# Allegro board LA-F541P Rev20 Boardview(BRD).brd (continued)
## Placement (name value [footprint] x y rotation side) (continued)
CT152  2.2U_0402_6.3V6M  [C_0402]  20.83 53.47 270 bottom
CT153  1U_0603_25V6  [C_0603]  26.06 65.83 180 bottom
CT157  1U_0603_25V6  [C_0603]  27.32 60.34 0 bottom
CT158  0.22U_0402_10V6K  [C_0402]  23.06 58.68 0 top
CT159  220P_0402_50V7K  [C_0402]  25.34 62.22 90 top
CT160  220P_0402_50V7K  [C_0402]  26.84 61.79 90 top
CT163  1U_0201_6.3V6M  [C_0201]  28.44 39.42 180 top
CT164  47U_0603_6.3V6M  [C_0603]  31.24 35.05 0 top
CT165  47U_0603_6.3V6M  [C_0603]  31.24 33.78 0 top
CT174  0.22U_0201_6.3V6M  [C_0201]  31.15 33.1 270 bottom
CT175  0.22U_0201_6.3V6M  [C_0201]  30.57 33.1 270 bottom
CT176  0.22U_0201_6.3V6M  [C_0201]  34.25 32.84 0 bottom
CT177  0.22U_0201_6.3V6M  [C_0201]  34.25 33.4 0 bottom
CT178  0.22U_0201_6.3V6M  [C_0201]  29.31 32.53 90 bottom
CT179  0.22U_0201_6.3V6M  [C_0201]  35.98 31.7 180 bottom
CT180  0.22U_0201_6.3V6M  [C_0201]  29.9 32.53 90 bottom
CT181  0.22U_0201_6.3V6M  [C_0201]  35.98 32.26 180 bottom
CT182  39P_0201_50V8J  [C_0201]  21.19 46.62 180 bottom
CT183  100P_0201_50V8J  [C_0201]  21.19 47.19 180 bottom
CT184  39P_0201_50V8J  [C_0201]  23.5 37.57 270 top
CT185  100P_0201_50V8J  [C_0201]  22.8 36.42 270 top
CT186  39P_0201_50V8J  [C_0201]  23.37 46.61 0 bottom
CT187  100P_0201_50V8J  [C_0201]  23.37 47.18 0 bottom
CT188  4.7U_0603_25V6K  [C_0603]  28.46 53.21 0 bottom
CT189  10U_0402_6.3V6M  [C_0402]  15.69 51.62 90 bottom
CV156  8.2P_0402_50V8D  [C_0402]  51.89 29.47 180 top
CV157  10U_0603_6.3V6M  [C_0603]  52.13 28.32 180 top
CV158  0.1U_0201_10V6K  [C_0201]  62.61 27.52 90 bottom
CV159  0.1U_0201_10V6K  [C_0201]  63.25 27.52 90 bottom
CV160  0.1U_0201_10V6K  [C_0201]  64.9 27.52 90 bottom
CV161  0.1U_0201_10V6K  [C_0201]  65.53 27.52 90 bottom
CV162  0.1U_0201_10V6K  [C_0201]  66.17 27.52 90 bottom
CV163  0.1U_0201_10V6K  [C_0201]  66.8 27.52 90 bottom
CV164  0.1U_0201_10V6K  [C_0201]  67.57 27.52 90 bottom
CV165  0.1U_0201_10V6K  [C_0201]  68.2 27.52 90 bottom
CV166  0.1U_0201_10V6K  [C_0201]  61.98 27.52 90 bottom
CV167  0.1U_0201_10V6K  [C_0201]  61.34 27.52 90 bottom
CV168  1000P_0402_50V7K  [C_0402]  42.55 34.21 90 top
CV169  0.1U_0402_25V6  [C_0402]  46.11 35.87 180 top
CV178  0.1U_0201_10V6K  [C_0201]  14.63 91.38 90 top
CV179  10U_0402_6.3V6M  [C_0402]  15.39 91.34 90 top
CV180  0.1U_0201_25V6K  [C_0201]  14.61 93.38 270 top
CV181  0.1U_0201_25V6K  [C_0201]  14.69 77.77 180 bottom
CV182  0.1U_0201_25V6K  [C_0201]  15.35 77.33 90 bottom
CV183  .1U_0402_16V7K  [C_0402]  55.17 30.07 180 bottom
CV184  8.2P_0402_50V8D  [C_0402]  53.69 29.15 270 bottom
CV499  0.1U_0402_10V7K  [C_0402]  245.89 48.05 90 top
CV794  0.1U_0402_10V7K  [C_0402]  235.59 52.38 90 top
CV796  1U_0402_6.3V6K  [C_0402]  236.48 52.38 90 top
CV798  4.7U_0603_6.3V6K  [C_0603]  237.62 52.26 90 top
CV817  0.1U_0402_10V7K  [C_0402]  208.64 51.66 0 top
CV818  0.22U_0201_6.3V6M  [C_0201]  191.42 65.95 180 top
CV819  0.22U_0201_6.3V6M  [C_0201]  191.42 65.31 180 top
CV820  0.22U_0201_6.3V6M  [C_0201]  193.07 66.96 180 top
CV821  0.22U_0201_6.3V6M  [C_0201]  193.07 66.33 180 top
CV822  0.22U_0201_6.3V6M  [C_0201]  191.42 67.35 180 top
CV823  0.22U_0201_6.3V6M  [C_0201]  191.42 67.98 180 top
CV824  0.22U_0201_6.3V6M  [C_0201]  193.07 69 180 top
CV825  0.22U_0201_6.3V6M  [C_0201]  193.07 68.36 180 top
CV826  0.22U_0201_6.3V6M  [C_0201]  191.42 69.38 180 top
CV827  0.22U_0201_6.3V6M  [C_0201]  191.42 70.01 180 top
CV828  0.22U_0201_6.3V6M  [C_0201]  193.07 71.03 180 top
CV829  0.22U_0201_6.3V6M  [C_0201]  193.07 70.39 180 top
CV830  0.22U_0201_6.3V6M  [C_0201]  191.42 71.41 180 top
CV831  0.22U_0201_6.3V6M  [C_0201]  191.42 72.04 180 top
CV832  0.22U_0201_6.3V6M  [C_0201]  193.07 73.06 180 top
CV833  0.22U_0201_6.3V6M  [C_0201]  193.07 72.43 180 top
CV834  0.22U_0201_6.3V6M  [C_0201]  191.42 74.08 180 top
CV835  0.22U_0201_6.3V6M  [C_0201]  191.42 73.44 180 top
CV836  0.22U_0201_6.3V6M  [C_0201]  193.07 74.46 180 top
CV837  0.22U_0201_6.3V6M  [C_0201]  193.07 75.09 180 top
CV838  0.22U_0201_6.3V6M  [C_0201]  191.42 76.11 180 top
CV839  0.22U_0201_6.3V6M  [C_0201]  191.42 75.47 180 top
CV840  0.22U_0201_6.3V6M  [C_0201]  194.02 77.06 180 top
CV841  0.22U_0201_6.3V6M  [C_0201]  194.02 76.43 180 top
CV842  0.22U_0201_6.3V6M  [C_0201]  192.5 78.14 180 top
CV843  0.22U_0201_6.3V6M  [C_0201]  192.5 77.51 180 top
CV844  0.22U_0201_6.3V6M  [C_0201]  194.02 79.16 180 top
CV845  0.22U_0201_6.3V6M  [C_0201]  194.02 78.52 180 top
CV846  0.22U_0201_6.3V6M  [C_0201]  192.5 79.47 180 top
CV847  0.22U_0201_6.3V6M  [C_0201]  192.5 80.11 180 top
CV848  0.22U_0201_6.3V6M  [C_0201]  194.02 80.49 180 top
CV849  0.22U_0201_6.3V6M  [C_0201]  194.02 81.13 180 top
CV850  0.1U_0402_10V7K  [C_0402]  220.23 79.16 0 top
CV851  0.1U_0402_10V7K  [C_0402]  204.38 64.8 0 top
CV852  0.1U_0402_10V7K  [C_0402]  201.04 63.57 270 top
CV853  0.1U_0402_10V7K  [C_0402]  227.18 47.27 0 top
CV854  0.1U_0402_10V7K  [C_0402]  201.9 61.8 180 top
CV855  10U_0402_6.3V6M  [C_0402]  201.17 54.87 0 bottom
CV856  22U_0402_6.3V6M  [C_0402]  201.17 56.14 0 bottom
CV857  12P_0201_50V8J  [C_0201]  218.15 51.82 0 top
CV858  15P_0201_50V8J  [C_0201]  217.46 51.82 180 top
CV859  4.7U_0402_6.3V6M  [C_0402]  199.65 74.99 180 top
CV860  4.7U_0402_6.3V6M  [C_0402]  200.45 73.22 180 top
CV861  4.7U_0603_6.3V6K  [C_0603]  224.85 117.35 0 top
CV862  22U_0402_6.3V6M  [C_0402]  227.14 61.09 270 bottom
CV863  22U_0603_6.3V6M  [C_0603]  221.11 88.52 270 top
CV864  10U_0603_6.3V6M  [C_0603]  218.44 88.2 0 top
CV865  4.7U_0402_6.3V6M  [C_0402]  200.36 77.47 180 top
CV866  4.7U_0402_6.3V6M  [C_0402]  194.7 61.76 90 top
CV867  4.7U_0603_6.3V6K  [C_0603]  224.85 116.1 0 top
CV868  10U_0603_6.3V6M  [C_0603]  222.35 118.52 270 bottom
CV869  22U_0603_6.3V6M  [C_0603]  196.53 87 90 top
CV870  22U_0603_6.3V6M  [C_0603]  221.64 80.57 0 top
CV871  22U_0402_6.3V6M  [C_0402]  225.74 61.09 270 bottom
CV872  22U_0603_6.3V6M  [C_0603]  222.25 82.23 0 top
CV873  10U_0603_6.3V6M  [C_0603]  222.44 86.81 90 top
CV874  1U_0402_6.3V6K  [C_0402]  201.72 68.87 0 top
CV875  1U_0402_6.3V6K  [C_0402]  202.03 76.8 0 top
CV876  1U_0402_6.3V6K  [C_0402]  201.85 70.8 0 top
CV877  1U_0402_6.3V6K  [C_0402]  201.85 71.76 0 top
CV878  4.7U_0603_6.3V6K  [C_0603]  193.87 83.21 180 top
CV879  4.7U_0603_6.3V6K  [C_0603]  197.5 84.62 90 top
CV880  10U_0603_6.3V6M  [C_0603]  192.46 82.01 0 top
CV881  10U_0603_6.3V6M  [C_0603]  200.53 75.2 0 top
CV882  22U_0603_6.3V6M  [C_0603]  199.52 84.04 0 top
CV883  10U_0603_6.3V6M  [C_0603]  201.54 80.6 270 top
CV884  10U_0603_6.3V6M  [C_0603]  214.9 67.3 270 top
CV885  1U_0402_6.3V6K  [C_0402]  216.79 69.78 270 top
CV886  1U_0402_6.3V6K  [C_0402]  204.37 81.57 180 top
CV887  1U_0402_6.3V6K  [C_0402]  205.92 79.81 90 top
CV888  1U_0402_6.3V6K  [C_0402]  215.98 67.44 270 top
CV889  1U_0402_6.3V6K  [C_0402]  207.46 79.87 90 top
CV890  1U_0402_6.3V6K  [C_0402]  204.43 79.16 180 top
CV891  0.1U_0402_10V7K  [C_0402]  198.95 66.6 90 top
CV892  0.1U_0402_10V7K  [C_0402]  214.4 64.54 180 top
CV893  0.1U_0402_10V7K  [C_0402]  221.68 63.06 0 top
CV894  1U_0402_6.3V6K  [C_0402]  221.55 64.54 90 top
CV895  4.7U_0603_6.3V6K  [C_0603]  220.03 63.93 90 top
CV896  10U_0603_6.3V6M  [C_0603]  224 64.38 270 top
CV897  10U_0603_6.3V6M  [C_0603]  225.3 64.38 270 top
CV898  1U_0402_6.3V6K  [C_0402]  202.62 79.12 270 top
CV899  1U_0402_6.3V6K  [C_0402]  223.52 88.2 270 top
CV900  1U_0402_6.3V6K  [C_0402]  218.23 74.58 90 top
CV901  1U_0402_6.3V6K  [C_0402]  210.87 79.95 90 top
CV902  1U_0402_6.3V6K  [C_0402]  213.16 79.95 0 top
CV903  1U_0402_6.3V6K  [C_0402]  210.14 79.1 180 top
CV904  0.1U_0402_10V7K  [C_0402]  211.74 63.94 90 top
CV905  0.1U_0402_10V7K  [C_0402]  212.63 63.94 90 top
CV906  1U_0402_6.3V6K  [C_0402]  213.16 52.71 0 top
CV907  4.7U_0603_6.3V6K  [C_0603]  212.15 52.58 180 top
CV917  0.1U_0402_25V6  [C_0402]  173.48 113.41 180 top
CV918  0.01UF_0402_25V7K  [C_0402]  175.13 110.64 0 top
CV919  0.01UF_0402_25V7K  [C_0402]  167.02 116.4 180 top
CV920  0.01UF_0402_25V7K  [C_0402]  247.91 52.12 90 top
CV921  0.1U_0402_10V7K  [C_0402]  208.35 80.09 270 top
CV922  0.1U_0402_10V7K  [C_0402]  215.97 72.35 270 top
CV923  0.1U_0402_10V7K  [C_0402]  214.77 79.06 180 top
CV924  22U_0603_6.3V6M  [C_0603]  192.62 85.23 0 top
CV925  0.01U_0201_16V7K  [C_0201]  239.47 105.92 180 top
CV926  820P_0402_25V7  [C_0402]  204.53 105.97 90 top
CV927  820P_0402_25V7  [C_0402]  224.58 109.76 90 top
CV928  0.01U_0201_16V7K  [C_0201]  199.39 102.2 90 top
CV929  1U_0402_6.3V6K  [C_0402]  209.04 100.53 270 top
CV930  1U_0402_6.3V6K  [C_0402]  208.4 109.41 0 top
CV931  1U_0402_6.3V6K  [C_0402]  210.76 107.65 270 top
CV932  1U_0402_6.3V6K  [C_0402]  204.47 110.99 90 top
CV933  1U_0402_6.3V6K  [C_0402]  202.4 100.51 90 bottom
CV934  1U_0402_6.3V6K  [C_0402]  204.14 95.89 0 bottom
CV935  1U_0402_6.3V6K  [C_0402]  209.17 108.54 270 top
CV936  1U_0402_6.3V6K  [C_0402]  206.96 107.46 180 top
CV937  22U_0603_6.3V6M  [C_0603]  238.95 110.94 90 top
CV938  22U_0603_6.3V6M  [C_0603]  236.69 112.85 180 top
CV939  22U_0603_6.3V6M  [C_0603]  240.36 98.12 90 top
CV940  22U_0603_6.3V6M  [C_0603]  227.2 98.11 180 top
CV941  22U_0603_6.3V6M  [C_0603]  239.46 102.49 270 top
CV942  10U_0603_6.3V6M  [C_0603]  232.29 109.93 90 top
CV943  10U_0603_6.3V6M  [C_0603]  233.59 109.94 90 top
CV944  10U_0603_6.3V6M  [C_0603]  224.68 113.09 90 top
CV945  10U_0603_6.3V6M  [C_0603]  223.47 113.09 90 top
CV946  10U_0603_6.3V6M  [C_0603]  225.88 113.09 90 top
CV947  10U_0603_6.3V6M  [C_0603]  227.08 113.09 90 top
CV948  1U_0402_6.3V6K  [C_0402]  233.44 106.24 180 top
CV949  1U_0402_6.3V6K  [C_0402]  229.43 106.62 0 top
CV950  1U_0402_6.3V6K  [C_0402]  232.41 108.73 270 top
CV951  1U_0402_6.3V6K  [C_0402]  237.68 112.51 90 top
CV952  1U_0402_6.3V6K  [C_0402]  228.78 107.99 0 top
CV953  1U_0402_6.3V6K  [C_0402]  238.32 102.5 270 top
CV954  1U_0402_6.3V6K  [C_0402]  239.4 106.86 90 top
CV955  1U_0402_6.3V6K  [C_0402]  239.24 98.63 90 top
CV956  1U_0402_6.3V6K  [C_0402]  239.4 109.81 270 top
CV957  1U_0402_6.3V6K  [C_0402]  236.78 106.43 0 top
CV958  22U_0603_6.3V6M  [C_0603]  218.19 111.32 270 top
CV959  22U_0603_6.3V6M  [C_0603]  204.73 112.97 90 top
CV960  22U_0603_6.3V6M  [C_0603]  216.85 111.32 270 top
CV961  22U_0603_6.3V6M  [C_0603]  216.54 105.22 0 top
CV962  22U_0603_6.3V6M  [C_0603]  211.39 110.38 90 top
CV963  10U_0603_6.3V6M  [C_0603]  211.39 112.97 90 top
CV964  10U_0603_6.3V6M  [C_0603]  210.06 112.97 90 top
CV965  10U_0603_6.3V6M  [C_0603]  209.99 110.38 90 top
CV966  10U_0603_6.3V6M  [C_0603]  207.39 112.97 90 top
CV967  10U_0603_6.3V6M  [C_0603]  206.06 112.97 90 top
CV968  10U_0603_6.3V6M  [C_0603]  208.73 112.97 90 top
CV969  1U_0402_6.3V6K  [C_0402]  214.81 111.25 0 top
CV970  1U_0402_6.3V6K  [C_0402]  213.87 110.61 90 top
CV971  1U_0402_6.3V6K  [C_0402]  215.81 97.79 180 top
CV972  1U_0402_6.3V6K  [C_0402]  215.02 107.25 0 top
CV973  1U_0402_6.3V6K  [C_0402]  215.71 100.89 90 top
CV974  1U_0402_6.3V6K  [C_0402]  215.71 99.05 90 top
CV975  1U_0402_6.3V6K  [C_0402]  207.33 111.82 0 top
CV976  1U_0402_6.3V6K  [C_0402]  206.31 111.95 180 top
CV977  1U_0402_6.3V6K  [C_0402]  204.47 109.11 270 top
CV978  1U_0402_6.3V6K  [C_0402]  216.8 108.8 270 top
CV979  1U_0402_6.3V6K  [C_0402]  233.55 107.62 90 top
CV980  1U_0402_6.3V6K  [C_0402]  227.79 107.05 90 top
CV981  1U_0402_6.3V6K  [C_0402]  226.12 108.89 90 top
CV982  1U_0402_6.3V6K  [C_0402]  226.12 110.73 90 top
CV983  1U_0402_6.3V6K  [C_0402]  231.14 99.57 270 top
CV984  1U_0402_6.3V6K  [C_0402]  236.83 109.79 0 top
CV985  1U_0402_6.3V6K  [C_0402]  238.35 98.35 180 top
CV986  1U_0402_6.3V6K  [C_0402]  227.22 99.32 180 top
CV987  0.01U_0201_16V7K  [C_0201]  243.18 55.65 180 top
CV988  820P_0402_25V7  [C_0402]  241.53 91.05 180 top
CV989  820P_0402_25V7  [C_0402]  247.05 95.9 0 top
CV990  0.01U_0201_16V7K  [C_0201]  243.23 91.63 0 top
CV991  1U_0402_6.3V6K  [C_0402]  247.49 82.92 90 top
CV992  1U_0402_6.3V6K  [C_0402]  250.58 81.54 180 top
CV993  1U_0402_6.3V6K  [C_0402]  247.26 87.31 0 top
CV994  1U_0402_6.3V6K  [C_0402]  238.86 91.06 0 top
CV995  1U_0402_6.3V6K  [C_0402]  237.56 79.88 180 top
CV996  1U_0402_6.3V6K  [C_0402]  249.73 89.54 0 top
CV997  1U_0402_6.3V6K  [C_0402]  238 91.07 90 top
CV998  1U_0402_6.3V6K  [C_0402]  248.81 79.25 180 top
CV999  22U_0603_6.3V6M  [C_0603]  246.76 56.47 0 top
CV1000  22U_0603_6.3V6M  [C_0603]  246.51 61.74 0 top
CV1001  22U_0603_6.3V6M  [C_0603]  235.01 55.56 270 top
CV1002  22U_0603_6.3V6M  [C_0603]  248.1 68.01 180 top
CV1003  22U_0603_6.3V6M  [C_0603]  249.18 68.01 0 top
CV1004  10U_0603_6.3V6M  [C_0603]  250 58.1 90 top
CV1005  10U_0603_6.3V6M  [C_0603]  249.24 63.37 0 top
CV1006  10U_0603_6.3V6M  [C_0603]  249.24 61.98 0 top
CV1007  10U_0603_6.3V6M  [C_0603]  246 59.96 0 top
CV1008  10U_0603_6.3V6M  [C_0603]  246.44 54.61 0 top
CV1009  10U_0603_6.3V6M  [C_0603]  249.24 60.71 0 top
CV1010  1U_0402_6.3V6K  [C_0402]  245.57 61.91 180 top
CV1011  1U_0402_6.3V6K  [C_0402]  236.16 55.7 270 top
CV1012  1U_0402_6.3V6K  [C_0402]  239.14 55.7 270 top
CV1013  1U_0402_6.3V6K  [C_0402]  250.64 82.98 90 top
CV1014  1U_0402_6.3V6K  [C_0402]  240.03 55.7 270 top
CV1015  1U_0402_6.3V6K  [C_0402]  248.12 65.27 0 top
CV1016  1U_0402_6.3V6K  [C_0402]  238 55.7 270 top
CV1017  1U_0402_6.3V6K  [C_0402]  237.05 55.7 270 top
CV1018  1U_0402_6.3V6K  [C_0402]  243.97 66.23 0 top
CV1019  1U_0402_6.3V6K  [C_0402]  239.95 67.82 0 top
CV1020  22U_0603_6.3V6M  [C_0603]  247.27 92.08 90 top
CV1021  22U_0603_6.3V6M  [C_0603]  236.03 91.12 90 top
CV1022  22U_0603_6.3V6M  [C_0603]  238.49 79.68 0 top
CV1023  22U_0603_6.3V6M  [C_0603]  250 80.58 270 top
CV1024  22U_0603_6.3V6M  [C_0603]  247.46 86.11 180 top
CV1025  10U_0603_6.3V6M  [C_0603]  249.49 86.3 270 top
CV1026  10U_0603_6.3V6M  [C_0603]  236.03 94.13 90 top
CV1027  10U_0603_6.3V6M  [C_0603]  239.74 94.13 90 top
CV1028  10U_0603_6.3V6M  [C_0603]  237.26 94.13 90 top
CV1029  10U_0603_6.3V6M  [C_0603]  238.51 94.13 90 top
CV1030  10U_0603_6.3V6M  [C_0603]  240.96 94.13 90 top
CV1031  1U_0402_6.3V6K  [C_0402]  249.62 90.48 90 top
CV1032  1U_0402_6.3V6K  [C_0402]  245.03 90.45 180 top
CV1033  1U_0402_6.3V6K  [C_0402]  239.47 86.93 180 top
CV1034  1U_0402_6.3V6K  [C_0402]  249.68 82.98 90 top
CV1035  1U_0402_6.3V6K  [C_0402]  246.14 84.96 180 top
CV1036  1U_0402_6.3V6K  [C_0402]  243.41 87.31 180 top
CV1037  1U_0402_6.3V6K  [C_0402]  248.48 92.19 90 top
CV1038  1U_0402_6.3V6K  [C_0402]  237.11 91.07 90 top
CV1039  1U_0402_6.3V6K  [C_0402]  245.96 87.72 180 top
CV1040  1U_0402_6.3V6K  [C_0402]  239.54 84.08 180 top
CV1041  1U_0402_6.3V6K  [C_0402]  244.98 58.34 90 top
CV1042  1U_0402_6.3V6K  [C_0402]  244.86 68.07 0 top
CV1043  1U_0402_6.3V6K  [C_0402]  239.09 67.82 180 top
CV1044  1U_0402_6.3V6K  [C_0402]  246.41 63.56 90 top
CV1045  1U_0402_6.3V6K  [C_0402]  240.98 55.7 270 top
CV1046  1U_0402_6.3V6K  [C_0402]  237.25 67.84 180 top
CV1047  1U_0402_6.3V6K  [C_0402]  245.06 57.49 270 top
CV1048  1U_0402_6.3V6K  [C_0402]  246.51 65.39 90 top
CV1050  0.1U_0402_10V7K  [C_0402]  214.9 77.09 180 top
CV1051  0.1U_0402_10V7K  [C_0402]  219.41 79.62 180 top
CZ4  470P_0603_50V7K  [C_0603]  259.08 39.12 180 top
CZ6  470P_0603_50V7K  [C_0603]  259.08 40.39 180 top
CZ8  10U_0603_6.3V6M  [C_0603]  259.72 36.58 0 top
CZ9  10U_0603_6.3V6M  [C_0603]  258.33 43.49 0 top
CZ11  1U_0603_10V6K  [C_0603]  54.74 8.38 0 top
CZ12  1U_0603_10V6K  [C_0603]  262.05 41.21 180 top
CZ18  1U_0402_6.3V6K  [C_0402]  59.18 5.87 270 top
CZ19  0.1U_0402_10V7K  [C_0402]  62.75 4.92 0 top
CZ20  2200P_0402_25V7K  [C_0402]  55.37 3.28 180 top
CZ26  1U_0402_6.3V6K  [C_0402]  340.79 60.14 0 bottom
CZ28  0.1U_0402_10V7K  [C_0402]  181.12 81.22 180 top
CZ29  0.1U_0402_10V7K  [C_0402]  345.57 60.12 90 bottom
CZ31  2200P_0402_25V7K  [C_0402]  344.79 62.93 0 bottom
CZ37  470P_0603_50V7K  [C_0603]  235.46 9.59 270 top
CZ39  470P_0603_50V7K  [C_0603]  274.45 6.99 180 top
CZ41  1U_0201_10V6M  [C_0201]  51.73 30.23 180 top
CZ43  0.1U_0402_10V7K  [C_0402]  51.56 23.17 90 bottom
CZ44  1U_0402_6.3V6K  [C_0402]  54.61 29.16 270 bottom
CZ45  0.1U_0402_10V7K  [C_0402]  237.11 9.6 270 top
CZ46  0.1U_0402_10V7K  [C_0402]  277.75 10.59 90 top
CZ47  0.1U_0402_10V7K  [C_0402]  181.23 82.68 180 bottom
CZ49  0.1U_0402_10V7K  [C_0402]  174.48 66.73 90 top
CZ82  0.1U_0402_10V7K  [C_0402]  186.18 84.13 90 bottom
CZ86  0.1U_0402_10V7K  [C_0402]  181.23 84.57 90 bottom
CZ88  1U_0402_6.3V6K  [C_0402]  181.23 83.62 180 bottom
CZ96  1U_0402_6.3V6K  [C_0402]  181.8 86.41 90 top
CZ97  0.1U_0402_25V6  [C_0402]  180.59 87.31 180 top
CZ98  2200P_0402_25V7K  [C_0402]  211.21 47.94 180 top
CZ99  0.1U_0402_10V6K  [C_0402]  210.85 63.96 90 top
CZ100  2200P_0201_25V7K  [C_0201]  14.88 62.53 0 bottom
CZ101  0.1U_0201_10V6K  [C_0201]  15.88 59.56 90 bottom
CZ104  2200P_0402_25V7K  [C_0402]  4.83 15.75 180 bottom
CZ105  2200P_0402_25V7K  [C_0402]  122.94 15.24 180 top
CZ106  0.1U_0402_10V6K  [C_0402]  120.31 13.58 90 top
CZ588  0.1U_0402_10V6K  [C_0402]  107.11 54.99 0 top
CZ1501  0.1U_0402_10V7K  [C_0402]  126.35 12.95 180 top
CZ2154  4.7U_0603_6.3V6M  [C_0603]  244.72 10.31 180 top
CZ2155  100P_0402_25V8K  [C_0402]  241.63 53.09 180 top
CZ2156  0.1U_0402_10V6K  [C_0402]  126.37 67.77 270 top
CZ2157  1U_0201_10V6M  [C_0201]  58.68 30.27 270 top
D18  AZ5B25-01F_DFN0603P2Y2  [ESD101-B1-02ELS_TSSLP-2-4-2]  343.35 59.95 180 bottom
D74  AZ5B25-01F_DFN0603P2Y2  [ESD101-B1-02ELS_TSSLP-2-4-2]  343.35 45.4 270 bottom
D123  AZ5B25-01F_DFN0603P2Y2  [ESD8011MUT5G_X3DFN2-2]  327.11 70.55 180 bottom
D124  AZ5B25-01F_DFN0603P2Y2  [ESD8011MUT5G_X3DFN2-2]  328.14 70.55 0 bottom
D125  -  [AZ5B25-01F_DFN0603P2Y2]  19.85 97.94 270 bottom
D126  -  [AZ5B25-01F_DFN0603P2Y2]  19.85 99.04 90 bottom
D321  -  [RB751S40T1G_SOD523-2]  176.3 3.87 180 top
D322  RB751S40T1G_SOD523-2  [AZ5125-01HPR7G_SOD523-2]  281.69 8.53 270 top
D323  AZ5B25-01F_DFN0603P2Y2  [ESD8011MUT5G_X3DFN2-2]  320.68 37.25 90 bottom
D324  AZ5B25-01F_DFN0603P2Y2  [ESD8011MUT5G_X3DFN2-2]  312.55 34.76 270 bottom
DA2  AZ5123-01F.R7G_DFN1006P2X2  [AZ5123-01FPR7G_DFN1006P2X2]  13.51 53.24 0 bottom
DA3  AZ5123-01F.R7G_DFN1006P2X2  [AZ5123-01FPR7G_DFN1006P2X2]  3.52 45.25 180 bottom
DA4  AZ5123-01F.R7G_DFN1006P2X2  [AZ5123-01FPR7G_DFN1006P2X2]  4.32 45.47 270 top
DA5  AZ5123-01F.R7G_DFN1006P2X2  [AZ5123-01FPR7G_DFN1006P2X2]  4.65 59.1 90 bottom
DA7  RB751S40T1G_SOD523-2  [AZ5125-01HPR7G_SOD523-2]  14.16 44.16 270 top
DA9  AZ5123-01F.R7G_DFN1006P2X2  [AZ5123-01FPR7G_DFN1006P2X2]  14.96 46.52 270 top
DA14  RB751S40T1G_SOD523-2  [AZ5125-01HPR7G_SOD523-2]  12.96 44.16 270 top
DA56  -  [RB751S40T1G_SOD523-2]  164 112.9 0 top
DA57  -  [RB751S40T1G_SOD523-2]  251.75 47.25 0 top
DE4  -  [PESD5V0U2BT_SOT23-3]  200.03 11.41 180 bottom
DE5  -  [PESD5V0U2BT_SOT23-3]  187.43 14.23 270 top
DE7  -  [RB751S40T1G_SOD523-2]  99.04 34.93 0 top
DE8  -  [RB751S40T1G_SOD523-2]  337.72 48.2 180 bottom
DE9  -  [TVNST52302AB0_SOT523-3]  149.61 7.49 0 bottom
DH1  -  [RB751S40T1G_SOD523-2]  84.89 2.48 180 top
DH2  -  [RB751S40T1G_SOD523-2]  62.45 13.53 180 bottom
DI1  -  [RB751S40T1G_SOD523-2]  348.68 46.52 90 bottom
DI3  AZ5125-02S.R7G_SOT23-3  [AZ5125-02SPR7G_SOT23-3]  347.73 42.65 180 bottom
DI7  -  [AZ1045-04F_DFN2510P10E-10-9]  19.62 101.49 90 top
DI9  -  [AZ1045-04F_DFN2510P10E-10-9]  332.56 73.8 270 top
DI12  BAT54CW-7-F_SOT323-3~D  [BAT54CW-7-F_SOT323-3]  328.8 41.72 0 bottom
DI13  AZ5B75-01B.R7G_CSP0603P2Y2  [ESD108-B1-CSP0201_WLL-2-1-2]  317.29 33.15 0 bottom
DI14  -  [RB751S40T1G_SOD523-2]  307.75 14.86 180 top
DI15  -  [RB751S40T1G_SOD523-2]  248.44 9.21 180 top
DI16  -  [RB751S40T1G_SOD523-2]  246.74 10.48 0 top
DI17  AZ5B75-01B.R7G_CSP0603P2Y2  [ESD108-B1-CSP0201_WLL-2-1-2]  316.44 33.15 180 bottom
DL1  AZ5125-02S.R7G_SOT23-3  [AZ5125-02SPR7G_SOT23-3]  344.27 115.44 270 top
DN1  -  [RB751S40T1G_SOD523-2]  326.56 82.11 0 bottom
DN2  -  [RB751S40T1G_SOD523-2]  331.85 77.45 90 bottom
DN3  BAT54CW-7-F_SOT323-3~D  [BAT54CW-7-F_SOT323-3]  335.92 43.37 0 bottom
DT10  AZ4024-02S_SOT23-3~D  [PESD24VS2UT_SOT23-3]  14.1 70.93 0 bottom
DT12  AZ5B75-01B.R7G_CSP0603P2Y2  [ESD108-B1-CSP0201_WLL-2-1-2]  11.18 69.28 90 top
DT13  AZ5B75-01B.R7G_CSP0603P2Y2  [ESD108-B1-CSP0201_WLL-2-1-2]  11.18 68.58 270 top
DT14  AZ5B75-01B.R7G_CSP0603P2Y2  [ESD108-B1-CSP0201_WLL-2-1-2]  9.94 67.33 0 top
DT15  AZ5B75-01B.R7G_CSP0603P2Y2  [ESD108-B1-CSP0201_WLL-2-1-2]  11.18 67.06 90 top
DT16  AZ5B75-01B.R7G_CSP0603P2Y2  [ESD108-B1-CSP0201_WLL-2-1-2]  11.18 66.36 270 top
DT17  AZ5B75-01B.R7G_CSP0603P2Y2  [ESD108-B1-CSP0201_WLL-2-1-2]  9.98 65.13 0 top
DT18  AZ5B75-01B.R7G_CSP0603P2Y2  [ESD108-B1-CSP0201_WLL-2-1-2]  11.18 64.37 90 top
DT19  AZ5B75-01B.R7G_CSP0603P2Y2  [ESD108-B1-CSP0201_WLL-2-1-2]  11.18 63.69 270 top
DT20  AZ5B75-01B.R7G_CSP0603P2Y2  [ESD108-B1-CSP0201_WLL-2-1-2]  9.4 71.19 90 bottom
DT21  AZ5B75-01B.R7G_CSP0603P2Y2  [ESD108-B1-CSP0201_WLL-2-1-2]  9.4 70.49 270 bottom
DT22  AZ5B75-01B.R7G_CSP0603P2Y2  [ESD108-B1-CSP0201_WLL-2-1-2]  4.52 72.52 90 top
DT23  AZ5B75-01B.R7G_CSP0603P2Y2  [ESD108-B1-CSP0201_WLL-2-1-2]  7.61 73.61 90 top
DT24  AZ5B75-01B.R7G_CSP0603P2Y2  [ESD108-B1-CSP0201_WLL-2-1-2]  7.62 72.94 270 top
DT25  AZ5B75-01B.R7G_CSP0603P2Y2  [ESD108-B1-CSP0201_WLL-2-1-2]  7.75 60.07 90 top
DT26  AZ5B75-01B.R7G_CSP0603P2Y2  [ESD108-B1-CSP0201_WLL-2-1-2]  10.1 62.36 0 bottom
DT27  AZ5B75-01B.R7G_CSP0603P2Y2  [ESD108-B1-CSP0201_WLL-2-1-2]  9.4 62.36 180 bottom
DT28  -  [RB751S40T1G_SOD523-2]  8.38 66.65 90 bottom
DT29  -  [RB751S40T1G_SOD523-2]  28.93 49.7 0 top
DT174  BAT54LPS-7  [BZT52C15LP-7_DFN1006-2]  11.62 70.7 90 bottom
DT175  -  [AZ5B25-01F_DFN0603P2Y2]  15.75 88.58 90 top
DT176  -  [AZ5B25-01F_DFN0603P2Y2]  15.75 87.82 270 top
DT177  -  [AZ5B25-01F_DFN0603P2Y2]  14.86 86.93 90 top
DT178  -  [AZ5B25-01F_DFN0603P2Y2]  14.86 86.17 270 top
DT179  -  [AZ5B25-01F_DFN0603P2Y2]  14.86 83.38 90 top
DT180  -  [AZ5B25-01F_DFN0603P2Y2]  14.86 82.61 270 top
DT181  -  [AZ5B25-01F_DFN0603P2Y2]  15.75 85.03 90 top
DT182  -  [AZ5B25-01F_DFN0603P2Y2]  15.75 84.27 270 top
DV1  BAT54CW-7-F_SOT323-3~D  [BAT54CW-7-F_SOT323-3]  48.01 27.24 180 bottom
DV2  BAT54CW-7-F_SOT323-3~D  [BAT54CW-7-F_SOT323-3]  45.47 27.24 180 bottom
DV7  BAT54CW-7-F_SOT323-3~D  [BAT54CW-7-F_SOT323-3]  65.79 28.64 180 top
DV12  -  [IP4220CZ6_SC-74-6]  58.6 30.02 270 bottom
DV13  -  [BAT54CW-7-F_SOT323-3]  209.11 46.17 90 top
DV14  -  [RB751S40T1G_SOD523-2]  214.12 42.9 90 top
DV15  -  [RB751S40T1G_SOD523-2]  215.39 52.6 270 top
DV16  -  [BAT54CW-7-F_SOT323-3]  250.04 44.2 0 top
DZ59  -  [RB751S40T1G_SOD523-2]  125.22 67.35 90 top
FD1  FIDUCAL  [FIDUCIAL_C40M80]  343.22 7.49 0 top
FD2  FIDUCIAL  [FIDUCIAL_C40M80]  24.63 109.32 0 top
FD3  FIDUCAL  [FIDUCIAL_C40M80]  23.43 110.17 180 bottom
FD4  FIDUCIAL  [FIDUCIAL_C40M80]  343.22 7.49 180 bottom
FD5  FIDUCAL  [FIDUCIAL_C40M80]  221.36 98.05 180 bottom
FD6  FIDUCAL  [FIDUCIAL_C40M80]  144.84 100.01 0 top
H1  -  [H_2P3]  248.4 2.1 0 top
H2  -  [H_2P3]  29 106 0 top
H5  -  [H_3P9]  248.05 74 0 top
H9  -  [H_2P5]  248.7 119.9 0 top
H10  -  [H_2P5]  4 4.5 0 top
H11  -  [H_2P1N]  7.14 2.55 0 top
H12  -  [H_6P0N]  9.1 29.2 0 top
H13  -  [H_3P9]  138.92 103.59 0 top
H16  -  [H_3P9]  185.79 90.27 0 top
H17  -  [H_2P1X2P5N]  27.61 110.34 346 top
H23  -  [EMIST_SUL-12A2M_1P]  102.8 61.15 270 bottom
H24  -  [EMIST_SUL-12A2M_1P]  102.8 86.25 270 bottom
H25  -  [EMIST_SUL-12A2M_1P]  113 55.05 180 bottom
H37  -  [H_3P2]  14.7 2.92 0 top
H38  -  [H_3P2]  4.75 21.14 0 top
H39  -  [H_2P5]  121 119 0 top
H40  -  [H_2P5]  348 3.5 0 top
H41  -  [H_2P8]  208.3 5.02 0 top
H42  -  [H_2P8]  143.7 5.02 0 top
H43  -  [H_2P3]  326.32 76.45 0 top
H45  -  [H_3P9]  185.79 56.83 180 top
H46  -  [H_3P9]  127.75 60.52 0 top
H47  -  [H_6P0N]  342.9 29.2 0 top
H48  -  [H_4P1]  344 13.8 0 top
H49  -  [H_2P3]  343.2 120.5 0 top
H50  -  [CLIP_C6-PM]  337.76 117.95 180 bottom
H54  -  [CLIP_C5P5-NPM]  259.59 39.75 180 bottom
H55  -  [CLIP_C5P5-NPM]  75.23 33.89 180 bottom
H59  -  [H_2P9X2P1N]  348 7.3 0 top
JAPS  ACES_50506-01841-P01  [ACES_50506-01841-P01_18P]  178.62 7.94 180 bottom
JAUDIO  ACES_88028-3010M  [ACES_88028-3010M_30P]  4 17.65 0 top
JCR  T-SOL_156-1051902601  [T-SOL_156-1051902601_19P-T]  330.25 56.55 90 top
JDEG1  ACES_50521-01041-P01  [ACES_50521-01041-P01_10P]  313.02 31.88 180 bottom
JDIMM1  BELLW_SD-80886-1021  [BELLW_SD-80886-1021_260P-T]  107.37 27.85 180 bottom
JDIMM2  BELLW_SD-80886-1021  [BELLW_SD-80886-1021_260P-T]  183.68 27.85 180 bottom
JEDP1  ACES_59003-04006-001  [ACES_59003-04006-001_40P]  67.73 36.53 0 bottom
JFAN1  ACES_50224-00401-001  [ACES_50224-00401-001_4P]  94.6 35.73 0 bottom
JFAN2  ACES_50224-00401-001  [ACES_50224-00401-001_4P]  337.19 54.7 90 bottom
JFP  ACES_50521-00841-P01  [ACES_50521-00841-P01_8P-T]  318.1 35.59 0 bottom
JHDD  J-L_UCNR2234B020-0  [J-L_UCNR2234B020-0_20P]  231.36 10.99 0 bottom
JHDMI1  ACON_HMRB9-AK120C  [ACON_HMRB9-AK120C_19P]  11.77 79.93 270 top
JHP1  YUQIU_PJ567-F07J1BE-C  [YUQIU_PJ567-F07J1BE-C_6P]  10.8 56.87 90 top
JKB  E-T_6710K-Y15M-31L  [E-T_6710K-Y15M-31L_15P]  163.3 10.9 180 bottom
JLPDE1  ACES_50521-01041-P01  [ACES_50521-01041-P01_10P]  299.56 31.88 180 bottom
JNGFF1  CONCR_213AAAA32FA  [CONCR_213AAAA32FA_67P]  328.55 84.42 0 bottom
JNGFF2  CONCR_213MAAA32FA  [CONCR_213MAAA32FA_67P-T]  260.48 23.04 270 bottom
JRTC  E&T_3806K-F02N-03R  [E-T_3806K-F02N-03R_2P]  329.75 104.85 0 top
JSPI1  ACES_50521-01041-P01  [ACES_50521-01041-P01_10P]  115.57 6.61 180 bottom
JTAG1  @SHORT PADS~D  [SHORTPADS]  303.02 26.04 0 bottom
JTP  ACES_51524-0080N-001  [ACES_51524-0080N-001_8P]  193 11.3 180 bottom
JTS  ACES_50208-00601-P01  [ACES_50208-00601-P01_6P]  350.35 57.94 90 bottom
JTS1  ACES_50208-00801-003  [ACES_50208-00801-003_8P]  345.95 48.26 0 bottom
JUSB1  TAIWI_USB019-107CRL-TWD  [TAIWI_USB019-107CRL-TWD_10P-T]  14.68 107.2 270 top
JUSB2  TAIWI_USB019-107CRL-TWD  [TAIWI_USB019-107CRL-TWD_10P-T]  337.32 69.95 90 top
JUSBC1  JAE_DX07S024XJ2  [JAE_DX07S024XJ2_24P-T]  7.86 69.06 270 top
JXDP  SAMTE_BSH-030-01-L-D-A  [SAMTE_BSH-030-01-L-D-A_60P]  128.19 86.01 90 top
LA1  BLM15PX600SN1D_2P  [MURAT_BLM15PX600SN1D_2P]  12.34 36.83 0 top
LA2  BLM21PG600SN1D_0805~D  [MURAT_BLM21PG600SN1D_L0805_2P]  14.29 39.89 90 top
LA3  BLM15PX600SN1D_2P  [MURAT_BLM15PX600SN1D_2P]  15.11 39.92 270 bottom
LA4  BLM15BB220SN1D_2P  [MURAT_BLM15BB220SN1D_2P]  4.54 26.76 0 bottom
LA5  BLM15AX700SN1D_2P  [MURAT_BLM15AX700SN1D_2P]  8.85 59.12 180 bottom
LA6  BLM15AX700SN1D_2P  [MURAT_BLM15AX700SN1D_2P]  14.36 51.41 90 bottom
LA7  BLM15AX700SN1D_2P  [MURAT_BLM15AX700SN1D_2P]  14.96 48.41 270 top
LA8  BLM15AX700SN1D_2P  [MURAT_BLM15AX700SN1D_2P]  6.99 45.48 180 top
LED1  27-21-T3D-CP1Q2B16Y-3C_WHITE  [LED_LTW-270TLA_2P]  349 108.59 270 top
LED2  27-21-T3D-CP1Q2B16Y-3C_WHITE  [LED_LTW-270TLA_2P]  349 104.99 270 top
LED3  27-21-T3D-CP1Q2B16Y-3C_WHITE  [LED_LTW-270TLA_2P]  349 101.39 270 top
LED4  27-21-T3D-CP1Q2B16Y-3C_WHITE  [LED_LTW-270TLA_2P]  349 97.79 270 top
LED5  27-21-T3D-CP1Q2B16Y-3C_WHITE  [LED_LTW-270TLA_2P]  349 94.19 270 top
LED6  HT-F196BP5_WHITE  [LED_HT-F196BP5_2P]  335.21 120.25 180 top
LH1  BLM15PX221SN1D_2P  [MURAT_BLM15PX221SN1D_2P]  91.94 7.39 0 top
LH2  BLM15PX221SN1D_2P  [MURAT_BLM15PX221SN1D_2P]  101.69 23.63 90 top
LH3  BLM15PX221SN1D_2P  [MURAT_BLM15PX221SN1D_2P]  72.06 25.28 90 bottom
LH4  BLM15PX221SN1D_2P  [MURAT_BLM15PX221SN1D_2P]  102.82 22.6 180 bottom
LI1  MCM1012B900F06BP_4P  [INPAQ_MCM1012B900F06BP_4P]  343.8 42.8 0 bottom
LI2  MCM1012B900F06BP_4P  [INPAQ_MCM1012B900F06BP_4P]  328.09 67.87 90 bottom
LI5  MCM1012B900F06BP_4P  [INPAQ_MCM1012B900F06BP_4P]  20.83 100.58 270 bottom
LM1  PBY160808T-301Y-N_2P  [CHILI_PBY160808T-300Y-N_2P]  26.93 77.36 270 bottom
LM2  PBY160808T-301Y-N_2P  [CHILI_PBY160808T-300Y-N_2P]  20.96 68.45 90 bottom
LM3  PBY160808T-301Y-N_2P  [CHILI_PBY160808T-300Y-N_2P]  18.78 76.46 0 bottom
LM4  PBY160808T-301Y-N_2P  [CHILI_PBY160808T-300Y-N_2P]  24.75 68.68 0 bottom
LM5  PBY160808T-301Y-N_2P  [CHILI_PBY160808T-300Y-N_2P]  18.27 70.11 0 bottom
LN1  MCM1012B900F06BP_4P  [INPAQ_MCM1012B900F06BP_4P]  329.75 81.1 90 bottom
LT1  0.68UH_MLV-YT10NR68N-M1L_2.7A_30%  [MAG_MLV-YT10NR68N-M1L_2P]  23.23 49.15 180 bottom
LT12  CMMI21T-900Y-N_4P  [CHILI_CMMI21T-900Y-N_4P]  13.93 66.51 90 top
LT13  CMMI21T-900Y-N_4P  [CHILI_CMMI21T-900Y-N_4P]  10.42 72.86 90 top
LT14  LQM18PN1R0MFHD_2P  [CHILI_PBY160808T-300Y-N_2P]  16.85 41.22 90 bottom
LV22  MCM1012B900F06BP_4P  [INPAQ_MCM1012B900F06BP_4P]  58.39 25.49 90 bottom
LV23  PBY160808T-300Y-N_2P  [CHILI_PBY160808T-300Y-N_2P]  199.01 54.79 90 bottom
LV24  PBY160808T-300Y-N_2P  [KC_FBMA-L11-160808300LMA25T_2P]  191.39 85.23 90 top
MD3  AZ5B75-01B.R7G_CSP0603P2Y2  [ESD108-B1-CSP0201_WLL-2-1-2]  319.72 33.4 0 bottom
MD4  AZ5B75-01B.R7G_CSP0603P2Y2  [ESD108-B1-CSP0201_WLL-2-1-2]  321.25 33.4 180 bottom
ML17  CMMI21T-900Y-N_4P  [CHILI_CMMI21T-900Y-N_4P]  317.33 30.19 180 bottom
NOREF  -  []  326.32 76.45 0 top
NOREF#2  -  []  29 106 0 top
NOREF#3  -  []  121 119 0 top
NOREF#4  -  []  343.2 120.5 0 top
NOREF#5  -  []  282.78 177.23 0 top
NOREF#6  -  []  248.34 2.4 0 top
NOREF#7  -  []  14.7 2.92 0 top
NOREF#8  -  []  185.79 56.83 0 top
NOREF#9  -  []  248.05 74 0 top
NOREF#10  -  []  185.79 90.27 0 top
NOREF#11  -  []  158.26 -41.43 0 top
NOREF#12  -  []  208.3 5.02 270 top
NOREF#13  -  []  140.62 -42.19 0 top
NOREF#14  -  []  248.7 119.9 0 top
NOREF#15  -  []  143.7 5.02 270 top
NOREF#16  -  []  127.75 60.52 0 top
NOREF#17  -  []  4 4.5 0 top
NOREF#18  -  []  348 3.5 270 top
NOREF#19  -  []  154.21 31.97 0 top
NOREF#20  -  []  4.75 21.14 90 top
NOREF#21  -  []  201.05 14.86 0 top
NOREF#22  -  []  138.92 103.59 0 top
NOREF#23  -  []  208.89 -66.69 0 top
NOREF#24  -  []  344 13.8 0 top
NOREF#25  -  []  206.38 34.93 90 bottom
NOREF#26  -  []  68.28 70.77 180 bottom
NOREF#27  -  []  234.19 35.43 90 bottom
NOREF#28  -  []  148.46 46.61 180 bottom
NOREF#29  -  []  218.19 34.8 90 bottom
NOREF#30  -  []  83.48 11.82 180 bottom
PC106  0.1U_0402_25V6  [C_0402]  25.95 90.03 0 bottom
PC107  100P_0402_50V8J  [C_0402]  25.91 20.12 90 bottom
PC108  0.01UF_0402_25V7K  [C_0402]  26.8 20.12 90 bottom
PC109  1000P_0402_50V7K  [C_0402]  27.36 15.62 0 top
PC110  100P_0402_50V8J  [C_0402]  27.36 16.51 0 top
PC114  0.1U_0402_25V6  [C_0402]  27.45 81 0 bottom
PC115  0.1U_0402_25V6  [C_0402]  27.45 82.02 0 bottom
PC200  0.01U_0402_25V7K~D  [C_0402]  24.87 3.78 270 top
PC201  0.022U_0603_50V7K  [C_0603]  16.38 29.59 180 bottom
PC202  0.022U_0603_50V7K  [C_0603]  10.54 18.29 180 bottom
PC203  10U_0805_25V6K  [C_0805]  13.21 26.54 90 top
PC204  0.1U_0402_10V7K  [C_0402]  16.26 34.8 180 bottom
PC205  100P_0402_50V8J~D  [C_0402]  32.2 3.75 270 top
PC206  220P_0402_50V8J~D  [C_0402]  32.2 4.7 90 top
PC207  1200P_0402_50V7K  [C_0402]  31.57 1.88 0 top
PC208  1000P_0402_50V7K  [C_0402]  30.61 25.53 180 top
PC209  100P_0402_50V8J  [C_0402]  28.96 28.32 0 bottom
PC210  1500P_0402_50V7K  [C_0402]  21.64 28.32 0 top
PC211  0.47U_0603_25V6K  [C_0603]  23.05 24.26 180 top
PC212  1500P_0402_50V7K  [C_0402]  19.81 21.13 90 top
PC213  0.1U_0402_10V7K  [C_0402]  24.77 18.54 90 top
PC214  100P_0402_50V8J  [C_0402]  26.04 8.32 270 top
PC215  100P_0402_50V8J  [C_0402]  27.63 9.83 90 top
PC216  1200P_0402_50V7K  [C_0402]  24.89 5.59 270 top
PC217  0.01UF_0402_25V7K  [C_0402]  19.86 27.56 0 top
PC218  0.01U_0201_16V7  [C_0201]  77.34 29.57 135 top
PC219  1500P_0402_50V7K  [C_0402]  61.99 14.73 180 bottom
PC220  1U_0603_25V6K  [C_0603]  66.28 25.18 315 top
PC221  0.1U_0201_10V6K  [C_0201]  71.23 22.73 135 top
PC222  1U_0402_16V6K  [C_0402]  69.74 22.93 135 top
PC223  1U_0402_10V6K  [C_0402]  73.36 30.63 315 top
PC335  4.7U_0603_6.3V6M  [C_0603]  348.04 25.91 90 top
PC400  4.7U_0603_6.3V6M  [C_0603]  347.96 21.41 0 top
PC401  100P_0402_50V8J  [C_0402]  348.88 23.37 180 bottom
PC402  100P_0402_50V8J  [C_0402]  347.9 20.32 0 bottom
PC403  15P_0402_50V8J  [C_0402]  324.77 20.63 90 top
PC404  0.1U_0402_25V6  [C_0402]  325.66 20.63 90 top
PC405  2200P_0402_50V7K  [C_0402]  323.88 20.63 90 top
PC406  10U_0603_25V6M  [C_0603]  328.72 20.56 90 top
PC407  0.1U_0402_25V6  [C_0402]  321.98 20.62 90 top
PC408  2200P_0402_50V7K  [C_0402]  322.99 20.63 90 top
PC409  10U_0603_25V6M  [C_0603]  326.99 20.56 90 top
PC410  0.1U_0603_50V7K  [C_0603]  339.85 24.58 0 top
PC411  0.1U_0603_50V7K  [C_0603]  344.23 17.72 0 top
PC412  150U_B2_6.3VM_R35M  [C_B2]  327.76 26.53 90 top
PC413  150U_B2_6.3VM_R35M  [C_B2]  324.2 4.65 270 top
PC414  680P_0603_50V7K  [C_0603]  332.87 32.77 180 top
PC415  .1U_0402_16V7K  [C_0402]  338.14 21.99 270 top
PC416  .1U_0402_16V7K  [C_0402]  332.36 18.98 90 top
PC417  680P_0603_50V7K  [C_0603]  339.44 16.98 90 top
PC418  0.1U_0402_25V6  [C_0402]  340.58 21.48 180 top
PC419  4.7U_0603_6.3V6M  [C_0603]  340.82 20.33 180 top
PC420  100U_D_20VM_R55M  [C_D]  323.47 16.26 270 top
PC456  150U_B2_6.3VM_R35M  [C_B2]  321 4.65 270 top
PC500  2200P_0402_50V7K  [C_0402]  136.98 8.9 270 top
PC501  0.1U_0402_25V6  [C_0402]  136.98 8.9 270 bottom
PC502  0.1U_0201_10V6K  [C_0201]  130.68 9.7 180 bottom
PC503  10U_0603_25V6M  [C_0603]  138.24 9.02 0 bottom
PC504  680P_0603_50V7K  [C_0603]  126.56 2.8 180 bottom
PC505  2.2U_0402_6.3V6M  [C_0402]  132.33 3.03 0 top
PC506  220P_0402_50V8J  [C_0402]  133.2 2.95 90 bottom
PC507  22U_0805_6.3VAM  [C_0805]  121.92 4.41 270 bottom
PC508  22U_0805_6.3VAM  [C_0805]  121.92 4.41 270 top
PC509  22U_0805_6.3VAM  [C_0805]  123.7 4.41 270 bottom
PC510  22U_0805_6.3VAM  [C_0805]  123.7 4.41 270 top
PC511  0.1U_0402_25V6  [C_0402]  134.7 4.03 270 bottom
PC512  1U_0402_6.3V6K  [C_0402]  132.25 3.89 270 bottom
PC513  10U_0603_25V6M  [C_0603]  138.24 9.02 0 top
PC600  0.22U_0603_16V7K  [C_0603]  284.54 27.88 180 bottom
PC601  10U_0603_25V6M  [C_0603]  276.02 30.61 270 bottom
PC602  10U_0603_25V6M  [C_0603]  276.29 31.4 270 top
PC603  0.1U_0402_25V6  [C_0402]  274.96 30.05 270 top
PC604  2200P_0402_50V7K  [C_0402]  274.96 30.23 270 bottom
PC605  10U_0603_25V6M  [C_0603]  284.35 31.24 90 top
PC606  10U_0603_25V6M  [C_0603]  281.89 31.35 180 top
PC607  1U_0603_10V6K  [C_0603]  287.34 25.91 0 bottom
PC608  330U_D1_2VY_R9M  [C_D1]  258.26 28.37 90 bottom
PC609  .1U_0402_16V7K  [C_0402]  288.29 33.15 180 bottom
PC610  1U_0603_10V6K  [C_0603]  290.13 27.18 270 bottom
PC611  680P_0603_50V7K  [C_0603]  265.43 27.94 270 bottom
PC612  22P_0402_50V8J  [C_0402]  291.72 31.69 90 bottom
PC613  0.1U_0402_10V7K  [C_0402]  291.83 29.72 0 top
PC614  0.1U_0402_10V7K  [C_0402]  291.83 30.74 0 bottom
PC615  10U_0603_25V6M  [C_0603]  276.23 32.51 90 bottom
PC700  2200P_0402_50V7K  [C_0402]  196.22 111.46 270 bottom
PC701  0.1U_0402_25V6  [C_0402]  197.11 111.46 270 bottom
PC702  10U_0603_25V6M  [C_0603]  195.07 111.95 270 bottom
PC703  10U_0603_25V6M  [C_0603]  193.8 111.95 270 bottom
PC704  1U_0402_25V6K  [C_0402]  195.02 112.02 180 top
PC705  1000P_0402_50V7K  [C_0402]  195.02 112.9 180 top
PC706  2.2U_0402_16V6K  [C_0402]  191.77 113.87 270 top
PC707  0.1U_0402_25V6  [C_0402]  192.72 119.81 90 top
PC708  0.22U_0603_25V7K  [C_0603]  198.88 115.63 90 top
PC709  680P_0402_50V7K  [C_0402]  207.19 120.65 0 top
PC710  0.1U_0402_25V6  [C_0402]  196.91 118.42 90 top
PC711  0.1U_0402_25V6  [C_0402]  193.68 119.81 90 top
PC712  2200P_0402_50V7K  [C_0402]  187.5 120.78 0 top
PC713  47P_0402_50V8J  [C_0402]  190.58 118.87 180 top
PC714  0.1U_0402_25V6  [C_0402]  188.72 118.03 90 top
PC715  2200P_0402_50V7K  [C_0402]  211.71 115.27 270 bottom
PC716  .1U_0402_16V7K  [C_0402]  210.82 115.27 270 bottom
PC717  22U_0805_6.3VAM  [C_0805]  213.17 115.34 270 bottom
PC718  330U_B2_2.5VM_R9M  [C_B2]  211.57 117.48 270 bottom
PC719  22U_0805_6.3VAM  [C_0805]  210.82 118.15 90 top
PC721  22U_0805_6.3VAM  [C_0805]  213.17 115.34 270 top
PC722  22U_0805_6.3VAM  [C_0805]  212.6 118.15 90 top
PC723  22U_0603_6.3V6M  [C_0603]  214.12 118.81 90 bottom
PC724  22U_0603_6.3V6M  [C_0603]  214.12 118.81 90 top
PC725  0.1U_0201_25V6K  [C_0201]  184.95 117.73 180 top
PC800  2200P_0402_50V7K  [C_0402]  108.6 57.03 0 bottom
PC801  0.1U_0201_10V6K  [C_0201]  112.4 58.8 0 bottom
PC802  0.1U_0402_25V6  [C_0402]  108.6 57.03 0 top
PC803  10U_0603_25V6M  [C_0603]  106.86 58.42 180 bottom
PC804  680P_0603_50V7K  [C_0603]  106.94 63.18 270 top
PC805  2.2U_0402_6.3V6M  [C_0402]  109.86 64.69 90 bottom
PC806  220P_0402_50V8J  [C_0402]  107.82 65.61 270 bottom
PC807  22U_0805_6.3VAM  [C_0805]  116.33 60.71 270 bottom
PC808  22U_0805_6.3VAM  [C_0805]  116.33 60.71 270 top
PC809  22U_0805_6.3VAM  [C_0805]  118.11 60.69 270 top
PC810  22U_0805_6.3VAM  [C_0805]  118.11 60.72 270 bottom
PC811  0.1U_0402_25V6  [C_0402]  104.98 63.63 180 bottom
PC812  1U_0402_6.3V6K  [C_0402]  108.97 64.69 90 bottom
PC813  10U_0603_25V6M  [C_0603]  108.99 58.9 0 top
PC900  0.1U_0402_25V6  [C_0402]  242.32 117.86 90 bottom
PC901  2200P_0402_50V7K  [C_0402]  243.21 117.86 90 bottom
PC902  0.1U_0201_10V6K  [C_0201]  238.38 116.5 270 top
PC903  10U_0603_25V6M  [C_0603]  246.38 116.33 270 bottom
PC904  680P_0603_50V7K  [C_0603]  236.73 114.87 90 top
PC905  2.2U_0402_6.3V6M  [C_0402]  238.63 113.34 90 bottom
PC906  220P_0402_50V8J  [C_0402]  241.3 111.05 90 top
PC907  22U_0805_6.3VAM  [C_0805]  229.49 117.39 90 bottom
PC908  22U_0805_6.3VAM  [C_0805]  227.78 117.39 90 bottom
PC909  22U_0805_6.3VAM  [C_0805]  227.79 117.39 90 top
PC910  22U_0805_6.3VAM  [C_0805]  229.51 117.38 90 top
PC911  0.1U_0402_25V6  [C_0402]  244.43 111.96 270 bottom
PC912  1U_0402_6.3V6K  [C_0402]  240.41 111.96 270 bottom
PC913  10U_0603_25V6M  [C_0603]  244.73 116.21 270 bottom
PC1000  10U_0805_25VAK  [C_0805]  165.52 103.28 180 bottom
PC1001  10U_0805_25VAK  [C_0805]  168.44 108.08 0 top
PC1003  0.1U_0402_25V7K  [C_0402]  165.78 105.55 180 bottom
PC1004  2200P_0402_50V7K  [C_0402]  169.03 106.64 0 top
PC1005  0.1U_0402_25V7K  [C_0402]  168.78 118.58 90 bottom
PC1006  22U_0603_6.3VAM  [C_0603]  207.45 71.88 90 top
PC1007  22U_0603_6.3VAM  [C_0603]  209.42 75.63 90 top
PC1008  22U_0603_6.3VAM  [C_0603]  211.48 71.91 0 top
PC1009  22U_0603_6.3VAM  [C_0603]  208.28 78.11 180 top
PC1010  22U_0603_6.3VAM  [C_0603]  206.25 67.93 270 top
PC1011  22U_0603_6.3VAM  [C_0603]  207.21 68.91 90 top
PC1012  22U_0603_6.3VAM  [C_0603]  204.08 78.08 0 top
PC1013  22U_0603_6.3VAM  [C_0603]  206.68 61.91 0 top
PC1014  22U_0603_6.3VAM  [C_0603]  204.09 71.18 0 top
PC1015  0.22U_0402_25V6K  [C_0402]  166.3 114.99 0 top
PC1016  22U_0603_6.3VAM  [C_0603]  206.8 64.31 0 top
PC1017  .01U_0402_16V7K  [C_0402]  167.9 118.58 90 bottom
PC1018  4700P_0402_25V7K  [C_0402]  164.69 119.37 180 bottom
PC1019  330U_B2_2.5VM_R9M  [C_B2]  180.36 95.25 0 bottom
PC1020  330U_B2_2.5VM_R9M  [C_B2]  185.83 95.4 270 bottom
PC1021  330U_B2_2.5VM_R9M  [C_B2]  185.83 102.68 90 bottom
PC1022  0.22U_0603_25V7K  [C_0603]  164.69 110.17 90 bottom
PC1023  4.7U_0603_6.3VAK  [C_0603]  204.03 73.41 0 top
PC1024  47P_0603_50V8J  [C_0603]  175.52 103.06 90 top
PC1025  4.7U_0603_6.3VAK  [C_0603]  206.57 74.39 0 top
PC1026  4.7U_0603_6.3VAK  [C_0603]  206.73 63.11 0 top
PC1027  4.7U_0603_6.3VAK  [C_0603]  207.33 75.63 90 top
PC1028  4.7U_0603_6.3VAK  [C_0603]  209.55 67.99 270 top
PC1029  4.7U_0603_6.3VAK  [C_0603]  210.32 74.2 180 top
PC1030  2.2U_0402_6.3VAM  [C_0402]  165.74 111.46 270 bottom
PC1031  1U_0402_6.3VAK  [C_0402]  214.21 71.46 90 top
PC1032  1U_0402_6.3VAK  [C_0402]  207.19 65.52 180 top
PC1033  1U_0402_6.3VAK  [C_0402]  208.84 68.91 0 top
PC1034  1U_0402_6.3VAK  [C_0402]  203.56 67.97 180 top
PC1035  1U_0402_6.3VAK  [C_0402]  211.07 66.66 270 top
PC1036  1U_0402_6.3VAK  [C_0402]  214.2 68.23 0 top
PC1037  1U_0402_6.3VAK  [C_0402]  212.85 66.66 270 top
PC1038  1U_0402_6.3VAK  [C_0402]  215.72 74.67 0 top
PC1039  1U_0402_6.3VAK  [C_0402]  204.78 69.22 0 top
PC1040  1U_0402_6.3VAK  [C_0402]  213.84 66.66 270 top
PC1041  0.1U_0402_25V7K  [C_0402]  171.31 119.42 270 bottom
PC1042  10U_0805_25VAK  [C_0805]  165.52 101.43 270 bottom
PC1043  10U_0805_25VAK  [C_0805]  168.39 104.8 0 top
PC1045  0.1U_0402_25V7K  [C_0402]  165.77 104.63 180 bottom
PC1046  2200P_0402_50V7K  [C_0402]  165.88 104.81 180 top
PC1047  0.22U_0603_25V7K  [C_0603]  169.41 114.94 90 top
PC1048  4.7U_0603_6.3VAK  [C_0603]  184.82 97.82 90 top
PC1049  4.7U_0402_6.3V6M  [C_0402]  204.79 54.87 180 bottom
PC1050  4.7U_0402_6.3V6M  [C_0402]  204.79 56.14 180 bottom
PC1051  4.7U_0603_6.3VAK  [C_0603]  186.09 97.81 90 top
PC1052  4.7U_0603_6.3VAK  [C_0603]  187.35 97.81 90 top
PC1053  4.7U_0603_6.3VAK  [C_0603]  208.41 65.51 0 top
PC1054  100P_0402_50V8J  [C_0402]  170.97 117.27 270 bottom
PC1055  0.01U_0402_16V7K  [C_0402]  171.92 115.61 0 bottom
PC1056  47P_0603_50V8J  [C_0603]  173.36 116.71 270 top
PC1057  10U_0603_6.3VAM  [C_0603]  181.36 101.54 180 top
PC1058  10U_0603_6.3VAM  [C_0603]  184.82 101.78 0 top
PC1059  10U_0603_6.3VAM  [C_0603]  181.36 97.6 180 top
PC1060  10U_0603_6.3VAM  [C_0603]  184.82 103 0 top
PC1061  10U_0603_6.3VAM  [C_0603]  181.36 100.2 180 top
PC1062  10U_0603_6.3VAM  [C_0603]  181.36 98.87 180 top
PC1063  10U_0603_6.3VAM  [C_0603]  184.82 104.2 0 top
PC1064  22U_0603_6.3VAM  [C_0603]  181.36 106.74 180 top
PC1065  22U_0603_6.3VAM  [C_0603]  181.36 108.08 180 top
PC1066  22U_0603_6.3VAM  [C_0603]  181.36 102.87 180 top
PC1067  22U_0603_6.3VAM  [C_0603]  181.36 109.34 180 top
PC1068  22U_0603_6.3VAM  [C_0603]  181.36 110.56 180 top
PC1069  22U_0603_6.3VAM  [C_0603]  181.36 104.14 180 top
PC1070  22U_0603_6.3VAM  [C_0603]  181.36 105.45 180 top
PC1100  4700P_0402_25V7K  [C_0402]  111.1 110.49 0 top
PC1101  1U_0402_10V6K  [C_0402]  117.54 111.7 90 top
PC1102  0.22U_0603_16V7K  [C_0603]  118.62 111.55 90 top
PC1103  330P_0402_50V7K  [C_0402]  111.1 109.54 0 top
PC1104  47P_0402_50V8J  [C_0402]  111.1 107.63 0 top
PC1105  8200P_0402_25V7K  [C_0402]  108.78 106.74 0 bottom
PC1106  680P_0402_50V7K  [C_0402]  108.78 104.97 90 top
PC1107  0.01UF_0402_25V7K  [C_0402]  117.54 100.97 270 top
PC1108  2200P_0402_50V7K  [C_0402]  123.47 110.3 180 top
PC1109  0.01UF_0402_25V7K  [C_0402]  112.03 106.36 180 top
PC1110  .1U_0402_16V7K  [C_0402]  124.84 108.52 0 top
PC1111  0.033U_0402_16V7K  [C_0402]  123.41 109.53 180 bottom
PC1112  0.068U_0402_16V7K  [C_0402]  111.63 104.46 180 top
PC1113  2200P_0402_50V7K  [C_0402]  111.13 106.74 0 bottom
PC1114  330P_0402_50V7K  [C_0402]  122.56 105.73 0 top
PC1115  68P_0402_50V8J  [C_0402]  122.56 106.68 0 top
PC1116  330P_0402_50V7K  [C_0402]  124.83 107.63 0 top
PC1117  2200P_0402_50V7K  [C_0402]  122.56 104.84 0 bottom
PC1118  220P_0402_50V8J  [C_0402]  124.89 105.83 90 top
PC1119  .1U_0402_16V7K  [C_0402]  111.11 102.49 0 bottom
PC1120  0.022U_0402_25V7K  [C_0402]  120.31 100.98 270 top
PC1121  0.01UF_0402_25V7K  [C_0402]  122.56 108.52 0 top
PC1122  0.022U_0402_25V7K  [C_0402]  110.72 102.49 0 top
PC1123  0.022U_0402_25V7K  [C_0402]  119.39 100.97 270 top
PC1124  0.022U_0402_25V7K  [C_0402]  118.49 100.97 270 top
PC1125  0.022U_0402_25V7K  [C_0402]  110.72 103.44 0 top
PC1126  .1U_0402_16V7K  [C_0402]  118.68 98.68 270 top
PC1127  0.022U_0402_16V7K  [C_0402]  119.64 98.68 270 top
PC1128  2200P_0402_50V7K  [C_0402]  119.44 100.97 270 bottom
PC1129  330P_0402_50V7K  [C_0402]  113.86 100.97 270 top
PC1130  470P_0402_50V7K  [C_0402]  116.59 98.3 90 bottom
PC1131  68P_0402_50V8J  [C_0402]  115.7 100.97 270 top
PC1132  680P_0402_50V7K  [C_0402]  116.59 99.19 270 top
PC1133  0.15U_0402_16V7K  [C_0402]  112.04 104.46 180 bottom
PC1134  8200P_0402_25V7K  [C_0402]  115.63 98.3 90 bottom
PC1135  0.22U_0402_16V7K  [C_0402]  118.99 98.64 270 bottom
PC1136  0.1U_0402_25V6  [C_0402]  123.41 108.64 180 bottom
PC1137  0.1U_0402_10V7K  [C_0402]  113.93 114.56 180 top
PC1138  1000P_0402_50V7K  [C_0402]  109.55 108.59 180 top
PC1139  1000P_0402_50V7K  [C_0402]  111.13 108.59 0 bottom
PC1200  4.7U_0603_6.3VAK  [C_0603]  135.21 113.18 270 bottom
PC1201  0.1U_0402_25V7K  [C_0402]  135.48 115.74 90 bottom
PC1209  47P_0603_50V8J  [C_0603]  144.16 114.09 180 top
PC1210  100U_D_20VM_R55M  [C_D]  132.19 112.26 90 bottom
PC1211  10U_0805_25VAK  [C_0805]  137.81 118.63 0 top
PC1212  10U_0805_25VAK  [C_0805]  137.76 118.63 0 bottom
PC1213  0.1U_0402_25V7K  [C_0402]  138.16 117.31 0 bottom
PC1214  2200P_0402_50V7K  [C_0402]  138.12 116.31 0 top
PC1234  47P_0603_50V8J  [C_0603]  147.53 114.05 90 top
PC1235  10U_0805_25VAK  [C_0805]  154.49 118.18 270 top
PC1236  10U_0805_25VX7SK  [C_0805]  153.54 118.2 270 bottom
PC1237  0.1U_0402_25V6  [C_0402]  150.82 119.12 180 top
PC1238  2200P_0402_50V7K  [C_0402]  153.18 117.58 270 top
PC1251  10U_0805_25VAK  [C_0805]  162.67 117.74 270 bottom
PC1252  10U_0805_25VAK  [C_0805]  162.57 117.74 270 top
PC1253  0.1U_0402_25V7K  [C_0402]  160.12 118.51 180 top
PC1254  2200P_0402_50V7K  [C_0402]  161.23 117.42 270 top
PC1255  47P_0603_50V8J  [C_0603]  157.05 113.66 90 top
PC1256  100U_D_20VM_R55M  [C_D]  127.24 112.19 90 bottom
PC1277  1.5P_0402_50V8  [C_0402]  138.16 117.31 0 top
PC1288  4.7U_0603_6.3VAK  [C_0603]  148.51 120.61 180 bottom
PC1289  0.1U_0402_25V7K  [C_0402]  151.19 120.42 0 bottom
PC1290  4.7U_0603_6.3VAK  [C_0603]  157.94 120.35 180 bottom
PC1291  0.1U_0402_25V7K  [C_0402]  159.74 120.68 270 bottom
PC1292  1U_0603_25V6K  [C_0603]  136.77 110.1 270 bottom
PC1293  1U_0603_25V6K  [C_0603]  145.8 117.73 90 bottom
PC1294  1U_0603_25V6K  [C_0603]  154.99 117.82 270 bottom
PC1295  10U_B3_25VM_R0.1  [C_B3]  132.87 113.64 270 top
PC1296  10U_B3_25VM_R0.1  [C_B3]  135.66 117.12 90 top
PC1297  10U_B3_25VM_R0.1  [C_B3]  129.24 117.12 90 top
PC1298  10U_B3_25VM_R0.1  [C_B3]  132.45 117.12 90 top
PC1299  10U_B3_25VM_R0.1  [C_B3]  129.67 113.64 270 top
PC1302  1U_0603_25V6K  [C_0603]  104.06 78.75 0 bottom
PC1308  0.1U_0402_25V7K  [C_0402]  104.12 83.11 90 bottom
PC1313  0.1U_0402_25V6  [C_0402]  113.48 96.91 0 top
PC1315  10U_0805_25VAK  [C_0805]  106.85 85.18 0 top
PC1316  10U_0805_25VAK  [C_0805]  106.85 85.18 0 bottom
PC1317  2200P_0402_50V7K  [C_0402]  106.92 82.98 0 top
PC1318  680P_0603_50V7K  [C_0603]  111.76 77.85 270 top
PC1319  0.1U_0402_25V6  [C_0402]  107.4 86.51 0 top
PC1336  1U_0603_25V6K  [C_0603]  104.06 70.74 0 bottom
PC1337  0.1U_0402_25V7K  [C_0402]  104.8 77.74 270 bottom
PC1343  10U_0805_25VAK  [C_0805]  106.69 77.28 0 bottom
PC1344  10U_0805_25VAK  [C_0805]  106.68 77.22 0 top
PC1345  0.1U_0402_25V6  [C_0402]  106.96 78.58 0 bottom
PC1346  2200P_0402_50V7K  [C_0402]  107.34 78.56 0 top
PC1347  680P_0603_50V7K  [C_0603]  111.95 73.98 90 top
PC1355  0.1U_0402_25V6  [C_0402]  105.23 94.62 180 bottom
PC1356  10U_0805_25VAK  [C_0805]  107.06 96.48 0 top
PC1357  2200P_0402_50V7K  [C_0402]  105.6 94.62 180 top
PC1358  10U_0805_25VAK  [C_0805]  107.06 96.48 0 bottom
PC1364  1U_0402_10V6K  [C_0402]  113.78 94.88 0 top
PC1365  680P_0603_50V7K  [C_0603]  105.32 92.08 90 bottom
PC1501  0.1U_0402_25V7K  [C_0402]  185.47 116.72 180 bottom
PC1502  22U_0603_6.3VAM  [C_0603]  205.05 67.93 270 top
PC1503  22U_0603_6.3VAM  [C_0603]  211.08 68.07 0 top
PC1504  1U_0402_6.3VAK  [C_0402]  203.79 69.79 180 top
PC1505  10U_0805_25VAK  [C_0805]  199.68 108.46 0 bottom
PC1507  22U_0603_6.3VAM  [C_0603]  211.57 76.52 0 top
PC1508  1U_0402_6.3VAK  [C_0402]  212.79 69.77 90 top
PC1509  10U_0805_25VAK  [C_0805]  199.68 106.68 0 bottom
PC1510  0.1U_0402_25V7K  [C_0402]  195.48 108.24 180 top
PC1511  2200P_0402_50V7K  [C_0402]  195.48 109.13 180 top
PC1512  22U_0603_6.3VAM  [C_0603]  209.04 71.38 0 top
PC1513  22U_0603_6.3VAM  [C_0603]  212.85 75.25 180 top
PC1514  22U_0603_6.3VAM  [C_0603]  205.55 76.39 180 top
PC1515  1U_0402_6.3VAK  [C_0402]  208.9 72.8 0 top
PC1516  1U_0402_6.3VAK  [C_0402]  204.27 75.06 0 top
PC1517  4700P_0402_25V7K  [C_0402]  184.25 114.89 270 bottom
PC1518  .01U_0402_16V7K  [C_0402]  185.47 115.83 180 bottom
PC1519  0.22U_0603_25V7K  [C_0603]  192.03 113.35 90 bottom
PC1520  2.2U_0402_16V6K  [C_0402]  192.53 117.43 270 bottom
PC1521  47P_0603_50V8J  [C_0603]  188.53 104.33 90 top
PC1522  0.1U_0402_25V7K  [C_0402]  182.86 118.91 0 bottom
PC1523  10U_0603_6.3VAM  [C_0603]  193.93 102.85 180 top
PC1524  10U_0603_6.3VAM  [C_0603]  193.93 104.05 180 top
PC1525  10U_0603_6.3VAM  [C_0603]  193.93 101.6 180 top
PC1526  22U_0805_6.3VAM  [C_0805]  197.67 104.9 0 top
PC1527  22U_0805_6.3VAM  [C_0805]  195.32 105.21 90 top
PC1528  22U_0805_6.3VAM  [C_0805]  193.57 105.21 90 top
PC1529  330U_B2_2.5VM_R9M  [C_B2]  191.49 95.33 0 bottom
PC1530  330U_B2_2.5VM_R9M  [C_B2]  195.22 95.33 180 bottom
PC1531  100P_0402_50V8J  [C_0402]  186.33 119.13 0 bottom
PC1532  0.01U_0402_16V7K  [C_0402]  188.15 119.11 90 bottom
PC1600  2200P_0402_50V7K  [C_0402]  244.73 108.84 270 bottom
PC1601  0.1U_0201_10V6K  [C_0201]  242.29 103.18 180 bottom
PC1602  10U_0603_25V6M  [C_0603]  246.25 108.82 180 top
PC1603  0.1U_0402_25V6  [C_0402]  246.09 107.75 180 top
PC1604  680P_0603_50V7K  [C_0603]  241.3 97.6 270 bottom
PC1605  2.2U_0402_6.3V6M  [C_0402]  246.84 101.6 180 bottom
PC1606  220P_0402_50V8J  [C_0402]  248.8 101.41 90 bottom
PC1607  22U_0603_6.3VAM  [C_0603]  247.71 96.8 0 bottom
PC1608  22U_0603_6.3VAM  [C_0603]  247.71 99.32 0 bottom
PC1609  22U_0603_6.3VAM  [C_0603]  247.71 98.05 0 bottom
PC1610  22U_0603_6.3VAM  [C_0603]  247.71 95.58 0 bottom
PC1611  0.1U_0402_25V6  [C_0402]  248.84 106.3 0 bottom
PC1612  1U_0402_6.3V6K  [C_0402]  247.91 101.93 270 bottom
PC1613  10U_0603_25V6M  [C_0603]  245.87 109.21 270 bottom
PC1800  0.1U_0402_16V7K  [C_0402]  178.82 10.29 90 top
PC1801  22U_0603_6.3V6M  [C_0603]  180.51 10.76 90 bottom
PC1802  22P_0402_50V8J  [C_0402]  180.73 16.6 180 top
PC1803  22U_0603_6.3V6M  [C_0603]  183.62 15.04 270 top
PC1804  1U_0402_6.3V6K  [C_0402]  183.19 11.27 90 top
PC1900  10U_0603_25V6M  [C_0603]  55.12 8.64 90 bottom
PC1901  10U_0603_25V6M  [C_0603]  53.85 8.64 90 bottom
PC1902  10U_0603_25V6M  [C_0603]  50.86 2.41 0 top
PC1903  10U_0603_25V6M  [C_0603]  51.31 8.64 90 bottom
PC1904  10U_0603_25V6M  [C_0603]  50.04 8.64 90 bottom
PC1905  10U_0603_25V6M  [C_0603]  50.88 4.94 0 top
PC1906  10U_0603_25V6M  [C_0603]  50.86 3.68 0 top
PC1907  10U_0603_25V6M  [C_0603]  52.58 8.64 90 bottom
PC1908  10U_0603_25V6M  [C_0603]  50.86 1.91 0 bottom
PC1909  100U_D_20VM_R55M  [C_D]  34.28 24.77 270 bottom
